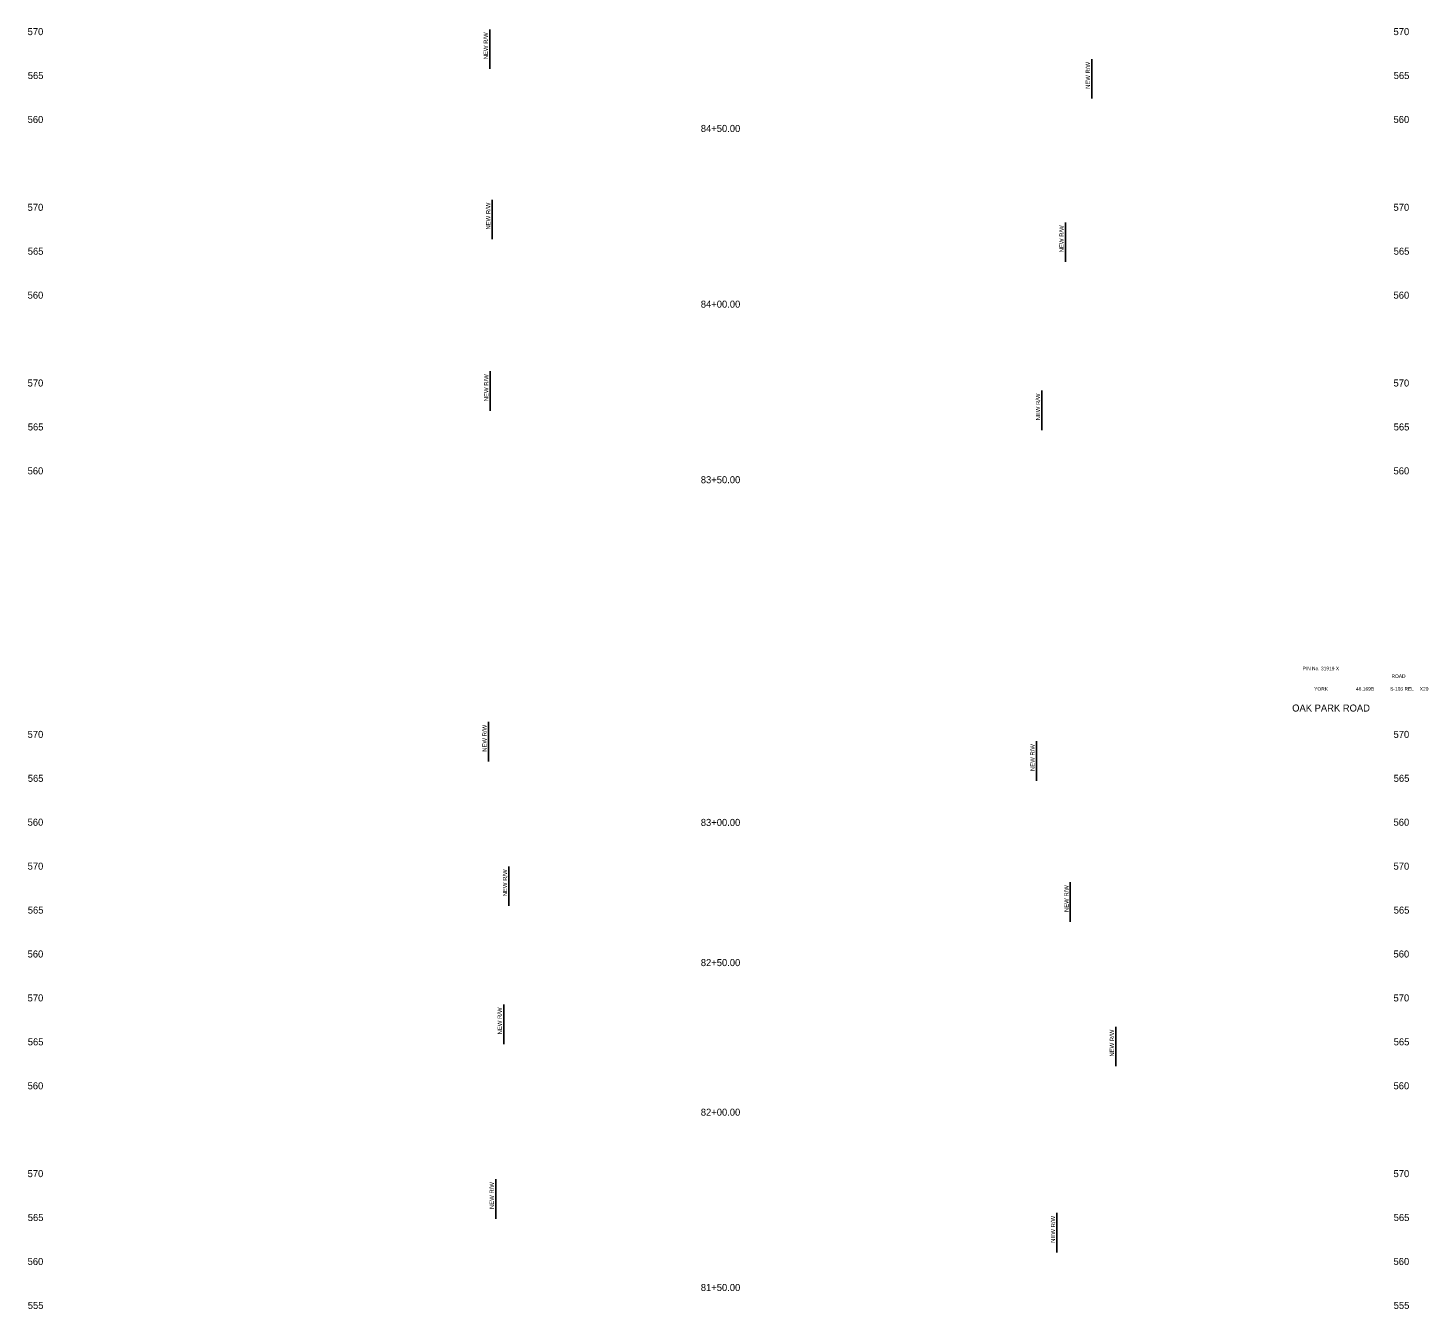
# Model space of a CAD drawing. Extents: x 1001 to 1161, y 1005 to 3518.
# Drawn here: x 1001.2 to 1160.6, y 3215.1 to 3360.9 of the extents above; entities that cross this region are included whole.
import ezdxf

# ---------------------------------------------------------------- set-up
doc = ezdxf.new("R2010")
doc.units = 0
for name, color, linetype in [('RD_SHT_TX', 7, 'Continuous'), ('RD_XS_NewRW', 7, 'Continuous'), ('RD_XS_TX_Elev_EX', 7, 'Continuous'), ('RD_XS_TX_Station', 7, 'Continuous')]:
    doc.layers.add(name, color=color, linetype=linetype)

msp = doc.modelspace()

# ---------------------------------------------------------------- linework, layer by layer
at = {"layer": 'RD_XS_NewRW'}
for p, q in [((1053.75, 3360.75), (1053.75, 3356.25)), ((1122.29, 3357.38), (1122.29, 3352.88)), ((1054.02, 3341.36), (1054.02, 3336.86)), ((1119.3, 3338.78), (1119.3, 3334.28)), ((1053.8, 3321.83), (1053.8, 3317.33)), ((1116.61, 3319.64), (1116.61, 3315.14)), ((1053.61, 3281.92), (1053.61, 3277.42)), ((1115.99, 3279.73), (1115.99, 3275.23)), ((1055.93, 3265.47), (1055.93, 3260.97)), ((1119.84, 3263.67), (1119.84, 3259.17)), ((1055.34, 3249.75), (1055.34, 3245.25)), ((1125.03, 3247.22), (1125.03, 3242.72)), ((1054.43, 3229.87), (1054.43, 3225.37)), ((1118.32, 3226.02), (1118.32, 3221.52))]:
    msp.add_line(p, q, dxfattribs=at)

# ---------------------------------------------------------------- texts
at = {"layer": 'RD_SHT_TX'}
for s, height, p in [('PIN No. 31919 X', 0.4, (1146.29, 3287.8)), ('ROAD', 0.4, (1156.41, 3286.93)), ('YORK', 0.4, (1147.61, 3285.48)), ('46.169B', 0.4, (1152.37, 3285.48)), ('S-103 REL', 0.4, (1156.26, 3285.48)), ('X20', 0.4, (1159.63, 3285.48)), ('OAK PARK ROAD', 0.8, (1145.1, 3283.1))]:
    msp.add_text(s, height=height, dxfattribs=at).set_placement(p)
at = {"layer": 'RD_XS_NewRW'}
for p in [(1053.55, 3357.35), (1122.09, 3353.98), (1053.82, 3337.96), (1119.1, 3335.38), (1053.6, 3318.43), (1116.41, 3316.24), (1053.41, 3278.52), (1115.79, 3276.33), (1055.73, 3262.07), (1119.64, 3260.27), (1055.14, 3246.35), (1124.83, 3243.82), (1054.23, 3226.47), (1118.12, 3222.62)]:
    msp.add_text('NEW R/W ', height=0.488, rotation=90, dxfattribs=at).set_placement(p)
at = {"layer": 'RD_XS_TX_Elev_EX'}
for s, p in [('570', (1001.14, 3360.1)), ('570', (1156.64, 3360.1)), ('565', (1001.16, 3355.1)), ('565', (1156.66, 3355.1)), ('560', (1001.14, 3350.1)), ('560', (1156.64, 3350.1)), ('570', (1001.14, 3340.1)), ('570', (1156.64, 3340.1)), ('565', (1001.16, 3335.1)), ('565', (1156.66, 3335.1)), ('560', (1001.14, 3330.1)), ('560', (1156.64, 3330.1)), ('570', (1001.14, 3320.1)), ('570', (1156.64, 3320.1)), ('565', (1001.16, 3315.1)), ('565', (1156.66, 3315.1)), ('560', (1001.14, 3310.1)), ('560', (1156.64, 3310.1)), ('570', (1001.14, 3280.1)), ('570', (1156.64, 3280.1)), ('565', (1001.16, 3275.1)), ('565', (1156.66, 3275.1)), ('560', (1001.14, 3270.1)), ('560', (1156.64, 3270.1)), ('570', (1001.14, 3265.1)), ('570', (1156.64, 3265.1)), ('565', (1001.16, 3260.1)), ('565', (1156.66, 3260.1)), ('560', (1001.14, 3255.1)), ('560', (1156.64, 3255.1)), ('570', (1001.14, 3250.1)), ('570', (1156.64, 3250.1)), ('565', (1001.16, 3245.1)), ('565', (1156.66, 3245.1)), ('560', (1001.14, 3240.1)), ('560', (1156.64, 3240.1)), ('570', (1001.14, 3230.1)), ('570', (1156.64, 3230.1)), ('565', (1001.16, 3225.1)), ('565', (1156.66, 3225.1)), ('560', (1001.14, 3220.1)), ('560', (1156.64, 3220.1)), ('555', (1001.16, 3215.1)), ('555', (1156.66, 3215.1))]:
    msp.add_text(s, height=0.8, dxfattribs=at).set_placement(p)
at = {"layer": 'RD_XS_TX_Station'}
for s, p in [('84+50.00', (1077.78, 3349.08)), ('84+00.00', (1077.78, 3329.08)), ('83+50.00', (1077.78, 3309.09)), ('83+00.00', (1077.78, 3270.08)), ('82+50.00', (1077.78, 3254.12)), ('82+00.00', (1077.78, 3237.09)), ('81+50.00', (1077.78, 3217.14))]:
    msp.add_text(s, height=0.8, dxfattribs=at).set_placement(p)

doc.saveas('drawing.dxf')
